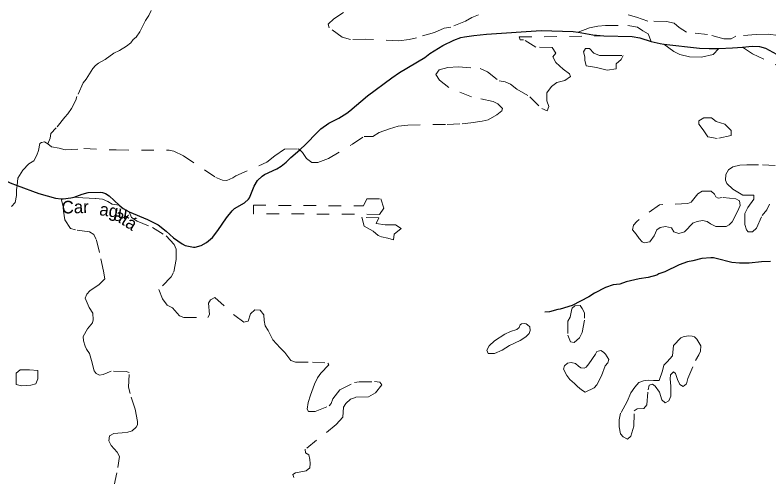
# Model space of a CAD drawing. Extents: x 344.9 to 371, y 7566.4 to 7594.3.
# Drawn here: x 353.71 to 359.71, y 7570.5 to 7574.18 of the extents above; entities that cross this region are included whole.
import ezdxf
from ezdxf.enums import TextEntityAlignment as Align

# ---------------------------------------------------------------- set-up
doc = ezdxf.new("R2010")
doc.units = 0
doc.header["$LTSCALE"] = 0.04
doc.linetypes.add('SHORT_DASHED', pattern=[2.7, 1.5, -1.2])
for name, color, linetype, lineweight in [('17', 7, 'SHORT_DASHED', 13), ('21', 7, 'SHORT_DASHED', 13), ('7', 7, 'Continuous', 25)]:
    doc.layers.add(name, color=color, linetype=linetype, lineweight=lineweight)
doc.layers.add('61', color=7, linetype='Continuous')

msp = doc.modelspace()

# ---------------------------------------------------------------- linework, layer by layer
at = {"layer": '17'}
for points in [[(354.7901, 7574.2118), (354.7718, 7574.1727), (354.7449, 7574.1324), (354.6998, 7574.042), (354.6717, 7574.0005), (354.6485, 7573.9822), (354.6277, 7573.9553), (354.5948, 7573.9284), (354.5386, 7573.893), (354.4922, 7573.8723), (354.425, 7573.8222), (354.3713, 7573.7929), (354.3481, 7573.774), (354.3274, 7573.7508), (354.2736, 7573.6653), (354.2504, 7573.636), (354.1992, 7573.5261), (354.1906, 7573.498), (354.1552, 7573.4314), (354.1271, 7573.3887), (354.1027, 7573.3631), (354.0343, 7573.2763), (353.9916, 7573.2324), (353.9867, 7573.1945), (353.9687, 7573.1502)], [(358.1925, 7574.0397), (358.2825, 7574.074), (358.3485, 7574.0884), (358.4105, 7574.0926), (358.588, 7574.0926), (358.6643, 7574.0802), (358.7077, 7574.0492), (358.749, 7574.0265), (358.7747, 7573.9654)]]:
    msp.add_lwpolyline(points, dxfattribs=at)
at = {"layer": '21'}
for points in [[(357.3974, 7574.1762), (357.3455, 7574.155), (357.2936, 7574.1267), (357.1781, 7574.0795), (357.1238, 7574.0701), (357.0484, 7574.0371), (356.9044, 7573.9948), (356.8455, 7573.9806), (356.763, 7573.9712), (356.4965, 7573.983), (356.3786, 7573.9806), (356.3125, 7573.9995), (356.2088, 7574.0749), (356.2017, 7574.1032), (356.2465, 7574.1457), (356.3243, 7574.1952)], [(359.7886, 7574.0134), (359.7061, 7574.0228), (359.6094, 7574.0204), (359.449, 7574.0087), (359.4113, 7573.9874), (359.3524, 7573.9851), (359.2227, 7574.0216), (359.0552, 7574.0381), (358.9963, 7574.0759), (358.9562, 7574.1112), (358.8949, 7574.1254), (358.7463, 7574.1277), (358.6567, 7574.1596), (358.5907, 7574.1784)], [(357.9418, 7573.4914), (357.9418, 7573.557), (357.9802, 7573.6067), (358.0232, 7573.6383), (358.0865, 7573.6541), (358.1317, 7573.6858), (358.1226, 7573.7061), (358.0729, 7573.7445), (358.0141, 7573.7965), (357.9915, 7573.8417), (358.0141, 7573.8711), (357.9848, 7573.9163), (357.856, 7573.9208), (357.7565, 7573.9795), (357.7294, 7573.9795), (357.7227, 7574.001), (358.3955, 7574.009)], [(358.8747, 7573.945), (358.9556, 7573.8863), (359.0023, 7573.861), (359.0802, 7573.8435), (359.1736, 7573.8396), (359.269, 7573.861), (359.3135, 7573.9084)], [(359.5008, 7573.9208), (359.5798, 7573.8664), (359.78, 7573.7725), (359.8357, 7573.7416), (359.8822, 7573.7354), (359.9568, 7573.7445)], [(355.9739, 7573.1005), (355.996, 7573.0813), (356.0276, 7573.0316), (356.0705, 7573.0022), (356.118, 7573.0022), (356.2039, 7573.0316), (356.3937, 7573.1468), (356.4887, 7573.2089), (356.5565, 7573.2089), (356.6084, 7573.2406), (356.6898, 7573.27), (356.7576, 7573.2903), (356.8344, 7573.2971), (357.0355, 7573.3039), (357.1486, 7573.3028), (357.2684, 7573.3095), (357.3384, 7573.3163), (357.4266, 7573.3299), (357.4763, 7573.3412), (357.5441, 7573.3796), (357.5848, 7573.4135), (357.5893, 7573.4316), (357.5531, 7573.4677), (357.5147, 7573.4881), (357.343, 7573.5242), (357.1622, 7573.5988), (357.0876, 7573.6575), (357.0582, 7573.7027), (357.0853, 7573.7389), (357.1531, 7573.757), (357.2367, 7573.7638), (357.4107, 7573.7502), (357.4695, 7573.7231), (357.5622, 7573.6508), (357.6096, 7573.644), (357.6526, 7573.6259), (357.7045, 7573.5852), (357.8085, 7573.5231), (357.9034, 7573.4304), (357.9464, 7573.4123), (357.9599, 7573.4462), (357.9418, 7573.4914)], [(353.7223, 7572.8187), (353.7283, 7572.8763), (353.7689, 7572.9404), (353.816, 7572.989), (353.8549, 7573.015), (353.8792, 7573.0604), (353.8922, 7573.0961), (353.9052, 7573.1513), (353.9182, 7573.1594), (353.9416, 7573.166), (353.9687, 7573.1502)], [(353.9687, 7573.1502), (353.9958, 7573.1253), (354.0568, 7573.1163), (354.1065, 7573.1005), (354.2557, 7573.1118), (354.5133, 7573.1005), (354.9337, 7573.0993), (354.9721, 7573.0925), (355.049, 7573.0541), (355.3066, 7572.8801), (355.3586, 7572.8598), (355.3947, 7572.8575), (355.4422, 7572.8778), (355.4648, 7572.8937), (355.7134, 7573.0033), (355.7767, 7573.0553), (355.8536, 7573.1084), (355.9621, 7573.1107), (355.9739, 7573.1005)], [(359.9606, 7572.9673), (359.6277, 7572.9829), (359.5362, 7572.9819), (359.4798, 7572.98), (359.4253, 7572.9664), (359.3902, 7572.943), (359.3688, 7572.9041), (359.3649, 7572.8593), (359.3766, 7572.834), (359.4253, 7572.7892), (359.5031, 7572.7406), (359.5927, 7572.7406), (359.5927, 7572.7094), (359.544, 7572.6432), (359.5206, 7572.5946), (359.5187, 7572.506), (359.5343, 7572.4651), (359.546, 7572.4495), (359.581, 7572.4476), (359.6121, 7572.4768), (359.6569, 7572.578), (359.6958, 7572.6228), (359.7173, 7572.6695)], [(353.6081, 7571.7586), (353.5951, 7571.8819), (353.5562, 7572.0279), (353.54, 7572.1293), (353.54, 7572.2299), (353.5709, 7572.4294), (353.5839, 7572.4773), (353.678, 7572.6492), (353.7072, 7572.6833), (353.7186, 7572.7368), (353.7186, 7572.7839), (353.7223, 7572.8187)], [(354.4074, 7571.311), (354.3803, 7571.3072), (354.3531, 7571.3188), (354.3376, 7571.3401), (354.3163, 7571.4235), (354.2988, 7571.4779), (354.2755, 7571.5128), (354.2639, 7571.538), (354.2522, 7571.5807), (354.2484, 7571.6156), (354.2834, 7571.6748), (354.3222, 7571.7233), (354.328, 7571.7485), (354.326, 7571.8009), (354.2969, 7571.8455), (354.264, 7571.9211), (354.2795, 7571.9522), (354.3028, 7571.9793), (354.3765, 7572.0278), (354.4212, 7572.0733), (354.4115, 7572.1354), (354.3805, 7572.2848), (354.3533, 7572.3876), (354.3339, 7572.4283), (354.3009, 7572.4497), (354.1884, 7572.4633), (354.1477, 7572.4749), (354.1031, 7572.5438), (354.0914, 7572.6136), (354.0914, 7572.6408), (354.075, 7572.7114)], [(354.1769, 7572.7249), (354.2477, 7572.7185), (354.3505, 7572.7147), (354.4029, 7572.7088), (354.4456, 7572.6914), (354.4805, 7572.67), (354.5354, 7572.6598)], [(354.6162, 7572.607), (354.6337, 7572.5614), (354.6784, 7572.5343), (354.8025, 7572.4819), (354.9092, 7572.4159), (354.9733, 7572.3471), (354.9907, 7572.3102), (354.9907, 7572.2287), (354.9694, 7572.124), (354.95, 7572.091), (354.8511, 7571.9882), (354.8821, 7571.9145), (354.9171, 7571.865), (354.9597, 7571.8418), (355.016, 7571.7797), (355.0509, 7571.7661), (355.243, 7571.7661), (355.2565, 7571.7894), (355.2488, 7571.8806), (355.2643, 7571.9077), (355.2992, 7571.9252), (355.4583, 7571.7807), (355.5301, 7571.7283), (355.5631, 7571.7361), (355.5825, 7571.7943), (355.6154, 7571.8272), (355.6601, 7571.8253), (355.6892, 7571.7884), (355.6911, 7571.7419), (355.6989, 7571.6992), (355.7241, 7571.6624), (355.7609, 7571.5886), (355.8172, 7571.5236), (355.856, 7571.4868), (355.9026, 7571.4227), (355.9414, 7571.4111), (356.0752, 7571.4111), (356.1993, 7571.4033), (356.2052, 7571.3888), (356.1412, 7571.3228), (356.1159, 7571.2859), (356.0927, 7571.2355), (356.0597, 7571.1482), (356.0422, 7571.0881), (356.0325, 7571.0357), (356.0442, 7571.0182), (356.0985, 7571.0163), (356.209, 7571.0609), (356.2246, 7571.0803), (356.2381, 7571.1172), (356.2925, 7571.1909), (356.4108, 7571.2471), (356.4476, 7571.253), (356.5699, 7571.2549), (356.6125, 7571.251), (356.628, 7571.2297), (356.5776, 7571.1667), (356.5214, 7571.1337), (356.4185, 7571.1298), (356.3778, 7571.1143), (356.341, 7571.0794), (356.3235, 7571.0522), (356.3177, 7570.9727), (356.2653, 7570.9125), (356.0171, 7570.7156), (356.019, 7570.6865), (356.0481, 7570.6729), (356.0559, 7570.6341), (356.0578, 7570.6031), (356.0539, 7570.5682), (356.0268, 7570.543)], [(359.0297, 7571.6127), (359.01, 7571.6029), (358.9528, 7571.5438), (358.9439, 7571.4598), (358.9009, 7571.4115), (358.8741, 7571.3865), (358.8634, 7571.3418), (358.8366, 7571.2649)], [(358.8401, 7571.1701), (358.858, 7571.1102), (358.8848, 7571.0852), (358.9134, 7571.1012), (358.9295, 7571.1388), (358.9295, 7571.2193), (358.9242, 7571.2783), (358.9277, 7571.3087), (358.9528, 7571.3337), (358.9689, 7571.3194), (358.9832, 7571.2729), (359.0011, 7571.2318), (359.0279, 7571.2157), (359.0547, 7571.2372), (359.0672, 7571.2801), (359.1262, 7571.4231), (359.1531, 7571.4679), (359.1674, 7571.4983), (359.1692, 7571.5394), (359.1388, 7571.593), (359.1203, 7571.6118), (359.1011, 7571.6171), (359.0673, 7571.6195), (359.0297, 7571.6127)], [(354.4966, 7570.4304), (354.5257, 7570.5701), (354.5373, 7570.6593), (354.5199, 7570.6932), (354.4714, 7570.7456), (354.4539, 7570.7844), (354.4598, 7570.8232), (354.4927, 7570.8407), (354.5975, 7570.8504), (354.6382, 7570.864), (354.6712, 7570.893), (354.6809, 7570.9105), (354.6809, 7570.9377), (354.6634, 7571.0366), (354.6227, 7571.1607), (354.6111, 7571.2121), (354.6169, 7571.3285), (354.5917, 7571.3363), (354.4714, 7571.3382), (354.4074, 7571.311)], [(358.7126, 7571.2605), (358.675, 7571.248), (358.6428, 7571.2105), (358.6107, 7571.1657), (358.5838, 7571.096), (358.5302, 7571.003), (358.5195, 7570.9512), (358.5195, 7570.8957), (358.5284, 7570.8385), (358.5499, 7570.8152), (358.5856, 7570.7956), (358.6124, 7570.8206), (358.6357, 7570.8993), (358.6375, 7571.0227), (358.6625, 7571.037), (358.7162, 7571.0406), (358.7394, 7571.071), (358.7501, 7571.1908), (358.7591, 7571.2266), (358.7841, 7571.2355), (358.8056, 7571.2176), (358.8401, 7571.1701)], [(358.8366, 7571.2649), (358.7931, 7571.2641), (358.7501, 7571.2677), (358.7126, 7571.2605)], [(356.0268, 7570.543), (355.9395, 7570.5274), (355.9201, 7570.5139), (355.9278, 7570.4906)]]:
    msp.add_lwpolyline(points, dxfattribs=at)
for points in [[(358.256, 7573.7701), (358.2448, 7573.8149), (358.2448, 7573.8429), (358.2336, 7573.8821), (358.2504, 7573.9101), (358.2839, 7573.9101), (358.3174, 7573.8709), (358.362, 7573.8541), (358.4402, 7573.8541), (358.5519, 7573.8541), (358.5351, 7573.8205), (358.496, 7573.7869), (358.496, 7573.7477), (358.4235, 7573.7365), (358.3397, 7573.7589)], [(359.1868, 7573.2604), (359.1533, 7573.3052), (359.1533, 7573.3333), (359.1924, 7573.3557), (359.2538, 7573.3557), (359.2929, 7573.3277), (359.3599, 7573.3052), (359.4102, 7573.2548), (359.4102, 7573.2156), (359.2985, 7573.1932), (359.2259, 7573.2044)], [(359.3385, 7572.722), (359.3067, 7572.718), (359.2888, 7572.728), (359.2788, 7572.7498), (359.253, 7572.7717), (359.1814, 7572.7737), (359.1456, 7572.7518), (359.0919, 7572.6842), (359.066, 7572.6743), (358.8393, 7572.6643), (358.6584, 7572.5311), (358.6325, 7572.5013), (358.6245, 7572.4635), (358.6544, 7572.4297), (358.6782, 7572.3959), (358.7021, 7572.37), (358.718, 7572.362), (358.7638, 7572.37), (358.7976, 7572.4177), (358.8194, 7572.4635), (358.8453, 7572.4834), (358.889, 7572.4913), (358.9348, 7572.4794), (358.9547, 7572.4495), (358.9944, 7572.4356), (359.0382, 7572.4495), (359.1098, 7572.5211), (359.1416, 7572.5311), (359.1834, 7572.539), (359.2192, 7572.5311), (359.247, 7572.5112), (359.2888, 7572.4913), (359.3703, 7572.4913), (359.3942, 7572.5032), (359.42, 7572.5291), (359.4618, 7572.6106), (359.4817, 7572.6584), (359.4777, 7572.6961), (359.4479, 7572.7121)], [(355.6048, 7572.5932), (355.6048, 7572.6604), (356.4814, 7572.6548), (356.5093, 7572.7108), (356.621, 7572.7108), (356.6433, 7572.638), (356.6098, 7572.5876)], [(356.4703, 7572.5652), (356.487, 7572.4924), (356.5596, 7572.4532), (356.5987, 7572.4196), (356.6266, 7572.4084), (356.6768, 7572.3972), (356.7215, 7572.386), (356.7271, 7572.4308), (356.7829, 7572.4756), (356.7383, 7572.5036), (356.6545, 7572.5036), (356.5819, 7572.5148), (356.6043, 7572.5596)], [(358.1429, 7571.8341), (358.1285, 7571.7692), (358.1093, 7571.7379), (358.1093, 7571.6248), (358.1309, 7571.5719), (358.1598, 7571.567), (358.2031, 7571.6031), (358.2248, 7571.6465), (358.244, 7571.7595), (358.244, 7571.8029), (358.2248, 7571.8389), (358.2079, 7571.8606), (358.1664, 7571.859), (358.1447, 7571.8405)], [(357.7026, 7571.6705), (357.6545, 7571.6537), (357.6088, 7571.632), (357.5246, 7571.5791), (357.4836, 7571.5406), (357.4644, 7571.5045), (357.4764, 7571.4804), (357.527, 7571.478), (357.5871, 7571.5045), (357.6449, 7571.543), (357.7315, 7571.5839), (357.7748, 7571.6128), (357.8013, 7571.6392), (357.8109, 7571.6633), (357.8061, 7571.6922), (357.79, 7571.7086), (357.778, 7571.7164), (357.765, 7571.7187), (357.7415, 7571.716), (357.7309, 7571.7065), (357.7212, 7571.6862)], [(358.3311, 7571.4733), (358.2778, 7571.3965), (358.2553, 7571.3703), (358.2394, 7571.3619), (358.2141, 7571.3637), (358.1944, 7571.3769), (358.171, 7571.3984), (358.1373, 7571.4087), (358.1073, 7571.4012), (358.0839, 7571.3806), (358.0745, 7571.3553), (358.1017, 7571.3038), (358.126, 7571.272), (358.1644, 7571.2411), (358.1869, 7571.2167), (358.2178, 7571.1905), (358.2487, 7571.1718), (358.319, 7571.2045), (358.3405, 7571.2289), (358.378, 7571.3001), (358.407, 7571.3806), (358.4276, 7571.4049), (358.437, 7571.4312), (358.4089, 7571.4733), (358.3939, 7571.4892), (358.3724, 7571.5042), (358.3415, 7571.4948)], [(353.7592, 7571.221), (353.7146, 7571.2322), (353.7146, 7571.2714), (353.7146, 7571.3218), (353.7481, 7571.3498), (353.8207, 7571.3498), (353.8877, 7571.3442), (353.8877, 7571.277), (353.8709, 7571.2378), (353.8318, 7571.2266)]]:
    msp.add_lwpolyline(points, close=True, dxfattribs=at)
at = {"layer": '7'}
for points in [[(355.9739, 7573.1005), (356.0242, 7573.146), (356.1123, 7573.2401), (356.1432, 7573.2685), (356.2064, 7573.3131), (356.2867, 7573.3548), (356.3485, 7573.3934), (356.3734, 7573.4114), (356.5146, 7573.5309), (356.7074, 7573.6765), (356.7688, 7573.7183), (356.9709, 7573.838), (357.0106, 7573.8685), (357.113, 7573.9327), (357.2025, 7573.975), (357.2583, 7573.9955), (357.2869, 7574.0024), (357.3603, 7574.0128)], [(357.3603, 7574.0128), (357.4622, 7574.0245), (357.8978, 7574.0513), (358.1538, 7574.0453), (358.1925, 7574.0397)], [(358.1925, 7574.0397), (358.3083, 7574.0176), (358.3955, 7574.009)], [(358.3955, 7574.009), (358.6216, 7574.0046), (358.6843, 7573.9929), (358.7747, 7573.9654)], [(358.7747, 7573.9654), (358.8457, 7573.9481), (358.8747, 7573.945)], [(358.8747, 7573.945), (359.159, 7573.9122), (359.2355, 7573.9082), (359.2683, 7573.9105), (359.3135, 7573.9084)], [(359.3135, 7573.9084), (359.4224, 7573.9132), (359.5008, 7573.9208)], [(359.5008, 7573.9208), (359.5792, 7573.9284), (359.6378, 7573.9249), (359.6858, 7573.9127), (359.7734, 7573.8635), (359.8579, 7573.8042)], [(352.8485, 7573.3304), (352.9414, 7573.2557), (352.9684, 7573.2462), (353.0716, 7573.2343), (353.0827, 7573.2311), (353.1192, 7573.2105), (353.213, 7573.1493), (353.2685, 7573.1215), (353.29, 7573.1072), (353.3424, 7573.0636), (353.39, 7573.0159), (353.4583, 7572.9572), (353.5051, 7572.9222), (353.5401, 7572.9), (353.6688, 7572.838), (353.7223, 7572.8187)], [(354.6162, 7572.607), (354.7624, 7572.547), (354.8473, 7572.5042), (354.9105, 7572.4551), (354.9686, 7572.4009), (355.0387, 7572.3522), (355.0609, 7572.3402), (355.1287, 7572.3252), (355.1425, 7572.3264), (355.1887, 7572.3402), (355.2307, 7572.3635), (355.28, 7572.4041), (355.3229, 7572.4583), (355.3912, 7572.5599), (355.4369, 7572.6155), (355.4554, 7572.6333), (355.5338, 7572.6806), (355.5656, 7572.7078), (355.5739, 7572.72), (355.6113, 7572.813), (355.6367, 7572.8571), (355.675, 7572.8924), (355.6948, 7572.9049), (355.7922, 7572.9492), (355.8277, 7572.9727), (355.8655, 7573.0043), (355.9029, 7573.0412), (355.9739, 7573.1005)], [(353.7223, 7572.8187), (353.8965, 7572.7544), (354.0293, 7572.7179), (354.075, 7572.7114)], [(354.1769, 7572.7249), (354.2415, 7572.7496), (354.2895, 7572.7623), (354.384, 7572.7639), (354.4034, 7572.7614), (354.4264, 7572.754), (354.4574, 7572.7355), (354.5354, 7572.6598)], [(354.075, 7572.7114), (354.0902, 7572.7107), (354.152, 7572.7184), (354.1769, 7572.7249)], [(354.5354, 7572.6598), (354.5668, 7572.6349), (354.6162, 7572.607)], [(359.7247, 7572.2132), (359.6527, 7572.2102), (359.555, 7572.1994), (359.4774, 7572.1991), (359.4166, 7572.2053), (359.292, 7572.2372), (359.2702, 7572.2401), (359.248, 7572.2417), (359.1781, 7572.2369), (359.1067, 7572.2187), (359.0622, 7572.2107), (358.9971, 7572.1845), (358.8839, 7572.1306), (358.835, 7572.113), (358.8192, 7572.1035), (358.7509, 7572.0853), (358.6794, 7572.0749), (358.5746, 7572.0495), (358.5254, 7572.032), (358.4714, 7572.0249), (358.411, 7572.005), (358.3221, 7571.9598)], [(358.3221, 7571.9598), (358.2776, 7571.9304), (358.1442, 7571.8621), (358.0489, 7571.8319), (358.0299, 7571.8295), (357.9648, 7571.8121), (357.9274, 7571.8089)]]:
    msp.add_lwpolyline(points, dxfattribs=at)

# ---------------------------------------------------------------- texts
at = {"layer": '61'}
for s, rotation, p in [('Car', 1.149, (354.1866, 7572.5962)), ('agu', 351.413, (354.484, 7572.5655)), ('atá', 327.597, (354.5609, 7572.5044))]:
    msp.add_text(s, height=0.1, rotation=rotation, dxfattribs=at).set_placement(p, align=Align.CENTER)

doc.saveas('drawing.dxf')
